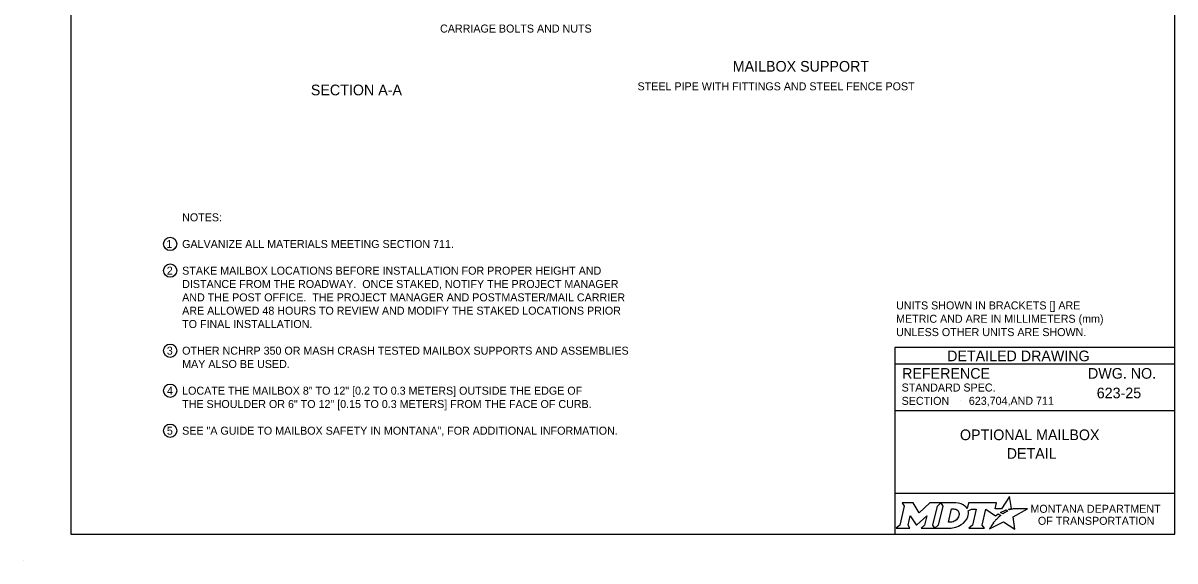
# Model space of a CAD drawing. Extents: x 49991.4 to 50021, y 49987.6 to 50011.4.
# Drawn here: x 49999.98 to 50008.61, y 49999.86 to 50003.9 of the extents above; entities that cross this region are included whole.
import ezdxf

# ---------------------------------------------------------------- set-up
doc = ezdxf.new("R2010")
doc.units = 0
doc.layers.add('Level 1', color=7, linetype='Continuous')
doc.layers.add('Level 2', color=7, linetype='Continuous')

msp = doc.modelspace()

# ---------------------------------------------------------------- linework, layer by layer
at = {"layer": 'Level 1'}
msp.add_line((49999.9766, 49999.8624), (49999.9766, 49999.8624), dxfattribs=at)
msp.add_lwpolyline([(50008.6146, 50011.2628), (50000.3356, 50011.2628), (50000.3356, 50000.0624), (50008.6146, 50000.0624)], close=True, dxfattribs=at)
at = {"layer": 'Level 2'}
for p, q in [((50008.6146, 50001.4624), (50006.5146, 50001.4624)), ((50006.5146, 50001.4624), (50006.5146, 50000.0624)), ((50008.6146, 50001.3374), (50006.5146, 50001.3374)), ((50008.2507, 50001.1223), (50008.2507, 50001.1223)), ((50008.6146, 50000.9874), (50006.5146, 50000.9874)), ((50007.0089, 50001.0629), (50007.0089, 50001.0629)), ((50007.5646, 50000.7383), (50007.5646, 50000.7383)), ((50008.6146, 50000.3693), (50006.5146, 50000.3693))]:
    msp.add_line(p, q, dxfattribs=at)
for points in [[(50006.5701, 50000.2974), (50006.5842, 50000.274), (50006.5507, 50000.1307), (50006.525, 50000.1082), (50006.6266, 50000.1082), (50006.6131, 50000.131), (50006.6293, 50000.2011), (50006.673, 50000.1321), (50006.6783, 50000.1321), (50006.7534, 50000.2016), (50006.737, 50000.1305), (50006.7123, 50000.1085), (50006.8139, 50000.1085), (50006.8001, 50000.1318), (50006.8333, 50000.2742)], [(50006.8333, 50000.2742), (50006.8586, 50000.2974), (50006.7762, 50000.2974), (50006.6966, 50000.2244), (50006.6521, 50000.2971), (50006.5701, 50000.2974)], [(50006.9722, 50000.2974), (50006.8586, 50000.2974), (50006.8733, 50000.2745), (50006.8394, 50000.1307), (50006.8139, 50000.1085), (50006.9245, 50000.1085)], [(50007.3771, 50000.2447), (50007.3668, 50000.2503), (50007.3784, 50000.2531), (50007.39, 50000.2551), (50007.3726, 50000.3452), (50007.3131, 50000.2539), (50007.2658, 50000.2532), (50007.2761, 50000.2973), (50007.0669, 50000.2974), (50007.0568, 50000.2549), (50007.051, 50000.2632)], [(50006.9962, 50000.2107), (50006.995, 50000.2026), (50006.9918, 50000.1933), (50006.9876, 50000.1851), (50006.982, 50000.1776), (50006.9755, 50000.1707), (50006.9676, 50000.1644), (50006.9593, 50000.1597), (50006.9502, 50000.1558), (50006.9411, 50000.1535), (50006.9319, 50000.1526), (50006.916, 50000.1526), (50006.9396, 50000.2526), (50006.9556, 50000.2526), (50006.9632, 50000.252), (50006.9708, 50000.2501), (50006.9774, 50000.2471), (50006.9835, 50000.2429), (50006.9883, 50000.2379), (50006.992, 50000.2319), (50006.9947, 50000.2257), (50006.9963, 50000.2183), (50006.9963, 50000.2153), (50006.9962, 50000.2107)], [(50007.0636, 50000.2383), (50007.0882, 50000.2514), (50007.1251, 50000.2514), (50007.0965, 50000.1309), (50007.069, 50000.1082), (50007.1852, 50000.1082), (50007.1682, 50000.1311), (50007.1964, 50000.2513), (50007.2677, 50000.1996), (50007.2888, 50000.2147), (50007.3085, 50000.2038)], [(50007.2527, 50000.1479), (50007.2374, 50000.1235), (50007.2327, 50000.116), (50007.2269, 50000.1074), (50007.2246, 50000.1031), (50007.3299, 50000.1562), (50007.4138, 50000.1011), (50007.4007, 50000.1938), (50007.5076, 50000.2522), (50007.4583, 50000.253), (50007.4282, 50000.2534), (50007.4074, 50000.2537), (50007.4006, 50000.2522), (50007.3957, 50000.251), (50007.3873, 50000.2487), (50007.3771, 50000.2447)], [(50007.3267, 50000.2171), (50007.3243, 50000.2154), (50007.306, 50000.225), (50007.3163, 50000.2307), (50007.3204, 50000.2329), (50007.329, 50000.2369), (50007.3347, 50000.2395), (50007.3426, 50000.2425), (50007.3499, 50000.2452), (50007.3617, 50000.2378), (50007.3577, 50000.2357), (50007.3531, 50000.2332), (50007.3489, 50000.231), (50007.3439, 50000.2281), (50007.342, 50000.227), (50007.3393, 50000.2254), (50007.3368, 50000.224), (50007.3345, 50000.2224), (50007.3319, 50000.2206), (50007.3292, 50000.2188), (50007.3267, 50000.2171)], [(50006.9702, 50000.1158), (50006.9786, 50000.1184), (50006.9916, 50000.1238), (50007.012, 50000.1348)], [(50007.2666, 50000.164), (50007.2666, 50000.164)]]:
    msp.add_lwpolyline(points, dxfattribs=at)
for centre in [(50001.0798, 50002.2396), (50001.0798, 50002.0396), (50001.0798, 50001.4392), (50001.0798, 50001.1392), (50001.0798, 50000.8392)]:
    msp.add_circle(centre, 0.05, dxfattribs=at)
for centre, radius, start, end in [((50006.9953, 50000.219), 0.0709, 339.53292, 15.85821), ((50006.9513, 50000.2363), 0.1183, 300.91025, 339.13831)]:
    msp.add_arc(centre, radius, start, end, dxfattribs=at)
for centre, major_axis, ratio, start_param, end_param in [((50006.9701, 50000.25), (0.0834, -0.0037), 0.568097, 0.61298, 1.570796), ((50007.0257, 50000.2573), (0.0361, -0.0295), 0.469099, 1.225588, 1.570796), ((50007.2974, 50000.1941), (-0.0112, -0.0097), 0.021651, 3.157348, 6.283185), ((50006.9248, 50000.2568), (0, 0.1484), 0.987302, 3.139398, 3.456847), ((50007.2597, 50000.1559), (-0.00694, -0.00806), 0.008222, 0, 3.137361), ((50007.2764, 50000.1742), (-0.0098, -0.0102), 0.016458, 3.141593, 6.279097)]:
    msp.add_ellipse(centre, major_axis=major_axis, ratio=ratio, start_param=start_param, end_param=end_param, dxfattribs=at)

# ---------------------------------------------------------------- texts
for s, height, p in [('CARRIAGE BOLTS AND NUTS', 0.06, (50003.1039, 50003.8247)), ('MAILBOX SUPPORT', 0.08, (50005.2983, 50003.5316)), ('SECTION A-A', 0.08, (50002.1348, 50003.3544)), ('STEEL PIPE WITH FITTINGS AND STEEL FENCE POST', 0.06, (50004.5848, 50003.3916)), ('NOTES:', 0.06, (50001.1698, 50002.4092)), ('1', 0.06, (50001.0516, 50002.2092)), ('GALVANIZE ALL MATERIALS MEETING SECTION 711.', 0.06, (50001.1698, 50002.2092)), ('2', 0.06, (50001.0546, 50002.0096)), ('STAKE MAILBOX LOCATIONS BEFORE INSTALLATION FOR PROPER HEIGHT AND', 0.06, (50001.1698, 50002.0092)), ('DISTANCE FROM THE ROADWAY.  ONCE STAKED, NOTIFY THE PROJECT MANAGER', 0.06, (50001.1698, 50001.9092)), ('AND THE POST OFFICE.  THE PROJECT MANAGER AND POSTMASTER/MAIL CARRIER ', 0.06, (50001.1698, 50001.8092)), ('ARE ALLOWED 48 HOURS TO REVIEW AND MODIFY THE STAKED LOCATIONS PRIOR ', 0.06, (50001.1698, 50001.7092)), ('UNITS SHOWN IN BRACKETS [] ARE ', 0.06, (50006.5233, 50001.7486)), ('TO FINAL INSTALLATION.', 0.06, (50001.1698, 50001.6092)), ('METRIC AND ARE IN MILLIMETERS (mm) ', 0.06, (50006.5233, 50001.6486)), ('UNLESS OTHER UNITS ARE SHOWN.', 0.06, (50006.5233, 50001.5486)), ('3', 0.06, (50001.0546, 50001.4092)), ('OTHER NCHRP 350 OR MASH CRASH TESTED MAILBOX SUPPORTS AND ASSEMBLIES', 0.06, (50001.1698, 50001.4092)), ('DETAILED DRAWING', 0.0799, (50006.9063, 50001.3599)), ('MAY ALSO BE USED.', 0.06, (50001.1698, 50001.3092)), ('REFERENCE', 0.08, (50006.5682, 50001.229)), ('DWG. NO.', 0.08, (50007.9624, 50001.229)), ('4', 0.06, (50001.0558, 50001.1092)), ('LOCATE THE MAILBOX 8" TO 12" [0.2 TO 0.3 METERS] OUTSIDE THE EDGE OF ', 0.06, (50001.1698, 50001.1092)), ('STANDARD SPEC.', 0.06, (50006.5649, 50001.133)), ('THE SHOULDER OR 6" TO 12" [0.15 TO 0.3 METERS] FROM THE FACE OF CURB.', 0.06, (50001.1698, 50001.0092)), ('SECTION', 0.06, (50006.5649, 50001.033)), ('5', 0.06, (50001.0549, 50000.8092)), ('SEE "A GUIDE TO MAILBOX SAFETY IN MONTANA", FOR ADDITIONAL INFORMATION.', 0.06, (50001.1698, 50000.8092)), ('OPTIONAL MAILBOX', 0.08, (50007.0023, 50000.7683)), ('DETAIL', 0.08, (50007.3527, 50000.6283)), ('MONTANA DEPARTMENT', 0.06, (50007.5308, 50000.2236)), ('OF TRANSPORTATION', 0.06, (50007.587, 50000.1336))]:
    msp.add_text(s, height=height, dxfattribs=at).set_placement(p)
for s, height, p in [('623-25', 0.08, (50008.0281, 50001.0819)), ('623,704,AND 711', 0.06, (50007.069, 50001.033))]:
    msp.add_text(s, height=height, rotation=0.1, dxfattribs=at).set_placement(p)

doc.saveas('drawing.dxf')
